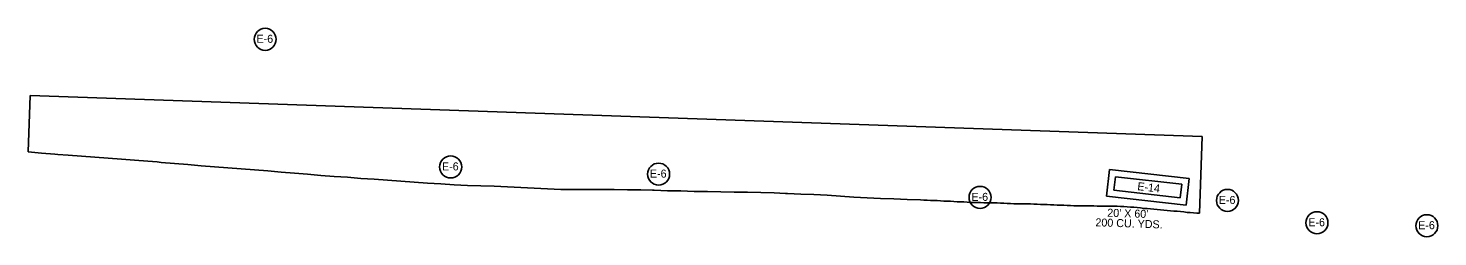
# Model space of a CAD drawing. Extents: x 881727 to 890277, y 1562105 to 1567179.
# Drawn here: x 886052 to 887109, y 1564390 to 1564546 of the extents above; entities that cross this region are included whole.
import ezdxf

# ---------------------------------------------------------------- set-up
doc = ezdxf.new("R2010")
doc.units = 0
for name, color, linetype in [('22', 7, 'Continuous'), ('Default', 7, 'Continuous'), ('R_Axis', 7, 'Continuous'), ('R_Water', 7, 'Continuous')]:
    doc.layers.add(name, color=color, linetype=linetype)

msp = doc.modelspace()

# ---------------------------------------------------------------- linework, layer by layer
at = {"layer": '22'}
for p, q in [((886051.5, 1564453.3), (886053, 1564495.4)), ((886053, 1564495.4), (886931.8, 1564464.8)), ((886931.8, 1564464.8), (886929.8, 1564407.2))]:
    msp.add_line(p, q, dxfattribs=at)
msp.add_lwpolyline([(886929.8, 1564407.2), (886927.9, 1564407.3), (886925.4, 1564407.5), (886922.9, 1564407.7), (886920.5, 1564407.9), (886918, 1564408.2), (886915.5, 1564408.5), (886913, 1564408.7), (886910.5, 1564408.9), (886908, 1564409.1), (886905.5, 1564409.3), (886903, 1564409.5), (886900.5, 1564409.8), (886898, 1564410.1), (886895.5, 1564410.3), (886893, 1564410.5), (886890.5, 1564410.7), (886888, 1564410.9), (886885.5, 1564411.2), (886883.1, 1564411.5), (886880.6, 1564411.7), (886878.1, 1564411.9), (886875.6, 1564412.1), (886873.1, 1564412.2), (886870.6, 1564412.3), (886868.1, 1564412.5), (886865.6, 1564412.6), (886863.1, 1564412.6), (886860.6, 1564412.6), (886858.1, 1564412.5), (886855.6, 1564412.5), (886853.1, 1564412.6), (886850.6, 1564412.7), (886848.1, 1564412.8), (886845.6, 1564412.9), (886843.1, 1564412.9), (886840.6, 1564412.8), (886838.1, 1564412.8), (886835.6, 1564412.9), (886833.1, 1564413), (886830.6, 1564413.1), (886828.1, 1564413.2), (886825.6, 1564413.3), (886823.1, 1564413.4), (886820.6, 1564413.5), (886818.1, 1564413.6), (886815.6, 1564413.7), (886813.1, 1564413.8), (886810.6, 1564413.9), (886808.1, 1564414), (886805.6, 1564414.1), (886803.1, 1564414.2), (886800.6, 1564414.3), (886798.1, 1564414.3), (886795.6, 1564414.4), (886793.1, 1564414.4), (886790.6, 1564414.4), (886788.1, 1564414.5), (886785.6, 1564414.6), (886783.1, 1564414.7), (886780.6, 1564414.8), (886778.1, 1564415), (886775.6, 1564415.1), (886773.1, 1564415.1), (886770.6, 1564415.1), (886768.1, 1564415.1), (886765.6, 1564415.2), (886763.1, 1564415.2), (886760.6, 1564415.3), (886758.1, 1564415.4), (886755.6, 1564415.6), (886753.1, 1564415.7), (886750.6, 1564415.8), (886748.1, 1564415.9), (886745.6, 1564416), (886743.1, 1564416.2), (886740.6, 1564416.3), (886738.1, 1564416.4), (886735.6, 1564416.5), (886733.1, 1564416.7), (886730.6, 1564416.8), (886728.1, 1564416.9), (886725.7, 1564417), (886723.2, 1564417.1), (886720.7, 1564417.2), (886710.7, 1564417.6), (886700.7, 1564418), (886690.7, 1564418.4), (886680.7, 1564418.8), (886670.7, 1564419.4), (886660.7, 1564420.1), (886650.7, 1564420.7), (886640.7, 1564421.2), (886630.8, 1564421.6), (886620.8, 1564422.1), (886619.5, 1564422.1), (886610.8, 1564422.4), (886600.8, 1564422.7), (886590.8, 1564423), (886580.8, 1564423.1), (886570.8, 1564423.2), (886560.8, 1564423.4), (886550.8, 1564423.6), (886540.8, 1564423.9), (886530.8, 1564424.1), (886520.8, 1564424.5), (886519.6, 1564424.5), (886510.8, 1564424.8), (886500.8, 1564424.8), (886490.8, 1564424.9), (886480.8, 1564425), (886470.8, 1564425), (886460.8, 1564425), (886450.8, 1564425.1), (886440.8, 1564425.6), (886430.8, 1564426.1), (886420.8, 1564426.5), (886410.8, 1564427), (886400.8, 1564427.4), (886390.8, 1564427.8), (886380.8, 1564428.1), (886370.8, 1564428.5), (886360.9, 1564429.2), (886350.9, 1564429.8), (886340.9, 1564430.6), (886330.9, 1564431.2), (886320.9, 1564431.9), (886310.9, 1564432.7), (886301, 1564433.3), (886291, 1564434.2), (886281, 1564434.8), (886271, 1564435.6), (886261, 1564436.4), (886251.1, 1564437.3), (886241.1, 1564438.1), (886231.1, 1564438.9), (886221.1, 1564439.7), (886211.2, 1564440.5), (886201.2, 1564441.3), (886191.2, 1564442), (886181.2, 1564442.8), (886171.2, 1564443.7), (886161.3, 1564444.5), (886151.3, 1564445.3), (886149.8, 1564445.4), (886148.1, 1564445.6), (886141.3, 1564446.1), (886131.3, 1564446.9), (886121.4, 1564447.7), (886111.4, 1564448.5), (886101.4, 1564449.2), (886091.4, 1564449.9), (886081.4, 1564450.7), (886073.8, 1564451.2), (886071.5, 1564451.4), (886061.5, 1564452.3), (886051.5, 1564453.3)], dxfattribs=at)
at = {"layer": 'Default'}
msp.add_circle((886229.2, 1564537.4), 8.26, dxfattribs=at)
at = {"layer": 'R_Water'}
for p, q in [((886860.2, 1564420), (886862.4, 1564439.9)), ((886862.4, 1564439.9), (886922, 1564433.3)), ((886865.7, 1564424.5), (886866.8, 1564434.4)), ((886866.8, 1564434.4), (886916.5, 1564428.9)), ((886916.5, 1564428.9), (886915.4, 1564418.9)), ((886922, 1564433.3), (886919.8, 1564413.4)), ((886919.8, 1564413.4), (886860.2, 1564420)), ((886915.4, 1564418.9), (886865.7, 1564424.5))]:
    msp.add_line(p, q, dxfattribs=at)
for centre in [(886368.3, 1564441.9), (886524.2, 1564436.5), (886765.3, 1564419.1), (886950.8, 1564416.8), (887017.9, 1564400.1), (887100.3, 1564397.9)]:
    msp.add_circle(centre, 8.26, dxfattribs=at)

# ---------------------------------------------------------------- texts
at = {"layer": 'Default'}
msp.add_text('E-6 ', height=6, dxfattribs=at).set_placement((886222.7, 1564534.8))
at = {"layer": 'R_Axis'}
for s, rotation, p in [('E-14', 353.6549, (886883, 1564424.6)), ("20' X 60'", 358.0903, (886860.6, 1564404.7)), ('200 CU. YDS. ', 358.0903, (886851.7, 1564397.5))]:
    msp.add_text(s, height=6, rotation=rotation, dxfattribs=at).set_placement(p)
at = {"layer": 'R_Water'}
for p in [(886361.8, 1564439.3), (886517.7, 1564433.9), (886758.8, 1564416.5), (886944.3, 1564414.2), (887011.4, 1564397.5), (887093.8, 1564395.3)]:
    msp.add_text('E-6 ', height=6, dxfattribs=at).set_placement(p)

doc.saveas('drawing.dxf')
